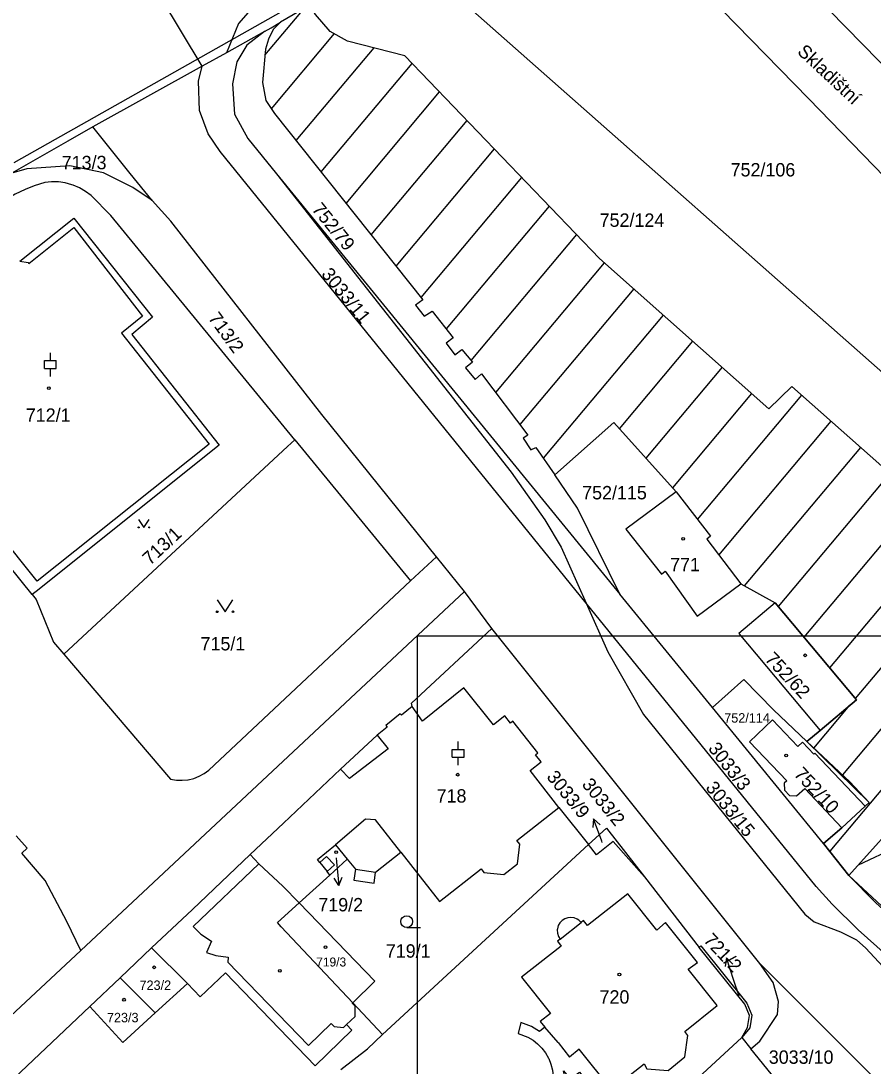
# Model space of a CAD drawing. Extents: x -496682 to -495776, y -1088797 to -1088018.
# Drawn here: x -496607.7 to -496499.5, y -1088218.9 to -1088086.1 of the extents above; entities that cross this region are included whole.
import ezdxf

# ---------------------------------------------------------------- set-up
doc = ezdxf.new("R2010")
doc.units = 0
for name, color, linetype in [('Hranice parcel', 7, 'Continuous'), ('Parcelní čísla', 7, 'Continuous'), ('Pop  PČ popisy', 7, 'Continuous'), ('Vnitřní kresba', 7, 'Continuous'), ('Vrstva 20', 7, 'Continuous'), ('Vrstva 54', 7, 'Continuous'), ('Vrstva 63', 7, 'Continuous'), ('Značky budov', 7, 'Continuous'), ('Značky kultur', 7, 'Continuous')]:
    doc.layers.add(name, color=color, linetype=linetype)

msp = doc.modelspace()

# ---------------------------------------------------------------- linework, layer by layer
at = {"layer": 'Hranice parcel'}
for p, q in [((-496584.7, -1088091.9), (-496593.73, -1088076.81)), ((-496571.02, -1088084.13), (-496574.77, -1088086.3)), ((-496580.1, -1088086.44), (-496581.64, -1088090.19)), ((-496576.81, -1088087.49), (-496581.64, -1088090.19)), ((-496581.64, -1088090.19), (-496584.7, -1088091.9)), ((-496584.7, -1088091.9), (-496598.59, -1088099.57)), ((-496585.17, -1088093.8), (-496584.7, -1088091.9)), ((-496575.26, -1088105.56), (-496531.65, -1088158.94)), ((-496572.95, -1088139.33), (-496586.65, -1088122.62)), ((-496572.95, -1088139.33), (-496558.23, -1088157.28)), ((-496554.95, -1088154.2), (-496558.23, -1088157.28)), ((-496551.4, -1088158.61), (-496554.95, -1088154.2)), ((-496583.85, -1088181.29), (-496558.23, -1088157.28)), ((-496521.83, -1088161.73), (-496516.3, -1088157.66)), ((-496516.3, -1088157.66), (-496511.91, -1088160.04)), ((-496600.11, -1088204.23), (-496551.4, -1088158.61)), ((-496547.92, -1088163.3), (-496551.4, -1088158.61)), ((-496519.86, -1088173.37), (-496531.65, -1088158.94)), ((-496513.88, -1088205.89), (-496547.92, -1088163.3)), ((-496602.29, -1088166.59), (-496588.72, -1088182.44)), ((-496505.76, -1088190.64), (-496519.86, -1088173.37)), ((-496506.2, -1088176.26), (-496507.89, -1088177.69)), ((-496539.38, -1088186.07), (-496535.62, -1088190.77)), ((-496500.47, -1088185.9), (-496503.43, -1088188.63)), ((-496503.43, -1088188.63), (-496505.76, -1088190.64)), ((-496606.96, -1088191.2), (-496608.33, -1088189.64)), ((-496561.79, -1088214.91), (-496535.62, -1088190.77)), ((-496566.28, -1088192.63), (-496568.5, -1088194.63)), ((-496572.41, -1088198.18), (-496568.5, -1088194.63)), ((-496528.52, -1088194.88), (-496521.57, -1088203.83)), ((-496600.11, -1088204.23), (-496610.33, -1088213.73)), ((-496591.15, -1088203.89), (-496595.15, -1088207.68)), ((-496591.15, -1088203.89), (-496586.58, -1088208.4)), ((-496595.15, -1088207.68), (-496598.99, -1088211.34)), ((-496595.15, -1088207.68), (-496590.7, -1088212.15)), ((-496586.58, -1088208.4), (-496590.7, -1088212.15)), ((-496598.99, -1088211.34), (-496611.67, -1088223.3)), ((-496561.79, -1088214.91), (-496565.59, -1088210.86)), ((-496516.14, -1088215.29), (-496545.84, -1088242.49)), ((-496516.14, -1088215.29), (-496515, -1088216.7)), ((-496510.2, -1088222.61), (-496515, -1088216.7))]:
    msp.add_line(p, q, dxfattribs=at)
for points in [[(-496529.16, -1088060.1), (-496522.91, -1088066.43), (-496519.74, -1088069.36), (-496513.72, -1088075.89), (-496502.91, -1088086.95), (-496490.59, -1088099.54)], [(-496539.32, -1088063.04), (-496541.74, -1088062.93), (-496544.5, -1088063.75), (-496558.08, -1088071.73), (-496573.82, -1088081.05), (-496576.28, -1088082.69), (-496577.99, -1088084.05), (-496580.1, -1088086.44)], [(-496539.03, -1088065.6), (-496535.97, -1088067.83), (-496531.62, -1088071.46), (-496507.63, -1088096.03), (-496473.26, -1088131.47)], [(-496559, -1088077.16), (-496484.87, -1088142.67), (-496473.26, -1088131.47)], [(-496449.81, -1088155.53), (-496454.1, -1088151.6), (-496460.56, -1088145.42), (-496469.27, -1088136.13), (-496476.41, -1088144.48), (-496483.29, -1088152.42), (-496496.71, -1088143.01), (-496497.27, -1088143.67), (-496509.81, -1088132.58), (-496512.72, -1088135.39), (-496534.24, -1088116.3), (-496558.95, -1088090.57), (-496566.25, -1088088.69), (-496568.44, -1088087.46), (-496570.32, -1088085.3), (-496571.02, -1088084.13)], [(-496574.77, -1088086.3), (-496575.71, -1088087.21), (-496576.29, -1088088.45), (-496576.66, -1088089.71), (-496577.03, -1088093.95), (-496576.63, -1088096.24), (-496575.54, -1088097.88), (-496556.69, -1088121.55), (-496557.59, -1088122.24), (-496556.5, -1088123.65), (-496555.48, -1088122.99), (-496552.81, -1088126.37), (-496553.73, -1088127.06), (-496552.61, -1088128.54), (-496551.71, -1088127.86), (-496550.38, -1088129.47), (-496551.26, -1088130.18), (-496550.05, -1088131.67), (-496549.21, -1088130.98), (-496543.32, -1088138.74), (-496543.92, -1088139.14), (-496542.96, -1088140.63), (-496542.32, -1088140.3), (-496539.92, -1088143.81)], [(-496576.81, -1088087.49), (-496575.96, -1088086.99), (-496574.77, -1088086.3)], [(-496576.81, -1088087.49), (-496579.05, -1088089.21), (-496580.3, -1088091.31), (-496580.87, -1088094.14), (-496580.61, -1088097.99), (-496578.92, -1088101.08), (-496575.26, -1088105.56)], [(-496535.94, -1088160.08), (-496582.43, -1088102.73), (-496583.94, -1088100.48), (-496585.03, -1088097.51), (-496585.17, -1088093.8)], [(-496598.59, -1088099.57), (-496601.77, -1088101.39), (-496608.89, -1088105.48)], [(-496591.05, -1088108.96), (-496593.86, -1088105.52), (-496598.59, -1088099.57)], [(-496591.05, -1088108.96), (-496593.52, -1088107.29), (-496597.24, -1088105.41), (-496601.51, -1088104.53), (-496607, -1088104.91), (-496608.89, -1088105.48)], [(-496598.83, -1088108.3), (-496599.53, -1088107.78), (-496600.29, -1088107.35), (-496601.08, -1088107.01), (-496601.29, -1088106.94), (-496602.12, -1088106.72), (-496602.98, -1088106.59), (-496603.85, -1088106.57), (-496604.72, -1088106.64), (-496606.05, -1088107.08), (-496607.21, -1088107.55), (-496608.47, -1088108.16), (-496609.68, -1088108.86), (-496610.16, -1088109.22), (-496610.57, -1088109.66), (-496610.74, -1088109.91), (-496611.03, -1088110.43), (-496611.23, -1088111), (-496611.33, -1088111.59)], [(-496575.26, -1088105.56), (-496545.47, -1088143.44), (-496541.17, -1088149.5), (-496539.1, -1088152.98), (-496535.94, -1088160.08)], [(-496586.65, -1088122.62), (-496596.3, -1088110.85), (-496598.83, -1088108.3)], [(-496554.95, -1088154.2), (-496569.51, -1088136.14), (-496588.7, -1088111.56), (-496591.05, -1088108.96)], [(-496607.87, -1088116.66), (-496601, -1088111.2), (-496591.02, -1088123.77), (-496593.66, -1088125.97), (-496582.54, -1088140.01), (-496605.81, -1088158.61), (-496606.3, -1088159)], [(-496606.3, -1088159), (-496617.15, -1088145.59), (-496618.65, -1088146.8), (-496619.26, -1088146.37), (-496619.37, -1088146.24), (-496621.25, -1088147.74), (-496621.51, -1088147.95), (-496621.62, -1088147.82), (-496622.15, -1088148.24), (-496627.2, -1088141.89), (-496626.66, -1088141.46), (-496626.77, -1088141.33), (-496626.5, -1088141.12), (-496624.56, -1088139.66), (-496624.44, -1088139.56), (-496628.56, -1088134.37)], [(-496539.92, -1088143.81), (-496532.42, -1088137.16), (-496524.49, -1088145.94)], [(-496602.29, -1088166.59), (-496573.88, -1088140.19), (-496572.95, -1088139.33)], [(-496531.65, -1088158.94), (-496537.04, -1088148.01), (-496539.92, -1088143.81)], [(-496524.49, -1088145.94), (-496530.88, -1088150.68), (-496526.37, -1088156.42)], [(-496524.49, -1088145.94), (-496520.15, -1088151.6), (-496520.61, -1088151.95), (-496516.3, -1088157.66)], [(-496526.37, -1088156.42), (-496525.89, -1088156.04), (-496521.83, -1088161.73)], [(-496606.3, -1088159), (-496605.78, -1088159.63), (-496603.61, -1088165.05), (-496602.29, -1088166.59)], [(-496535.94, -1088160.08), (-496533.17, -1088166.28), (-496528.64, -1088174.22), (-496508.14, -1088199.6), (-496506.98, -1088200.58), (-496503.63, -1088201.84), (-496501.59, -1088202.85), (-496500.38, -1088203.92), (-496493.36, -1088211.52), (-496474.31, -1088229.54), (-496444.2, -1088257.99), (-496416.61, -1088284.03), (-496413.37, -1088286.95)], [(-496413.37, -1088286.95), (-496422.7, -1088272.51), (-496424.74, -1088270.02), (-496501.36, -1088201.6), (-496504.67, -1088198.35), (-496506.73, -1088196.1), (-496535.94, -1088160.08)], [(-496511.91, -1088160.04), (-496516.53, -1088163.93), (-496506.2, -1088176.26)], [(-496511.91, -1088160.04), (-496501.59, -1088172.37), (-496506.2, -1088176.26)], [(-496558.05, -1088173.24), (-496558.11, -1088172.82), (-496547.92, -1088163.3)], [(-496507.89, -1088177.69), (-496512.14, -1088173.65), (-496515.88, -1088169.78), (-496519.86, -1088173.37)], [(-496539.38, -1088186.07), (-496543.06, -1088181.37), (-496541.64, -1088180.25), (-496542.35, -1088179.36), (-496542.05, -1088179.12), (-496545.24, -1088175.09), (-496545.54, -1088175.33), (-496546.26, -1088174.42), (-496547.71, -1088175.56), (-496551.45, -1088170.87), (-496556.73, -1088175.07), (-496558.05, -1088173.24)], [(-496558.05, -1088173.24), (-496559.39, -1088174.33), (-496559.54, -1088174.14), (-496561.39, -1088175.64), (-496561.23, -1088175.83), (-496562.5, -1088176.86), (-496567.13, -1088181.17), (-496574.38, -1088188.04), (-496578.61, -1088192.04), (-496585.95, -1088198.99), (-496591.15, -1088203.89)], [(-496500.47, -1088185.9), (-496506.88, -1088179.14), (-496507.01, -1088179.26), (-496508.45, -1088177.75), (-496509.05, -1088178.31), (-496512.25, -1088174.92), (-496515.17, -1088177.72), (-496510.42, -1088182.66), (-496510.78, -1088182.98), (-496510.72, -1088183.84), (-496510.09, -1088184.51), (-496509.22, -1088184.57), (-496508.15, -1088183.63), (-496503.43, -1088188.63)], [(-496507.89, -1088177.69), (-496502.43, -1088182.79), (-496499.96, -1088185.42), (-496500.47, -1088185.9)], [(-496588.72, -1088182.44), (-496587.99, -1088182.57), (-496587.25, -1088182.6), (-496586.52, -1088182.53), (-496586.5, -1088182.53), (-496585.78, -1088182.36), (-496585.09, -1088182.09), (-496584.44, -1088181.73), (-496583.85, -1088181.29)], [(-496566.28, -1088192.63), (-496565.24, -1088193.9), (-496565.43, -1088195.29), (-496562.87, -1088195.65), (-496562.68, -1088194.26), (-496559.49, -1088191.73), (-496554.58, -1088197.99), (-496549.28, -1088193.83), (-496548.95, -1088194.31), (-496546.38, -1088194.57), (-496544.64, -1088193.19), (-496544.34, -1088190.69), (-496544.73, -1088190.26), (-496539.38, -1088186.07)], [(-496502.56, -1088194.71), (-496494.62, -1088185.88), (-496475.92, -1088202.47), (-496475.59, -1088202.1), (-496472.44, -1088198.82), (-496390.14, -1088271.47), (-496393.43, -1088275.14), (-496397.84, -1088280.09)], [(-496535.62, -1088190.77), (-496533.34, -1088188.66), (-496528.52, -1088194.88)], [(-496600.11, -1088204.23), (-496601.92, -1088200.52), (-496604.66, -1088195.32), (-496607.61, -1088191.84), (-496606.96, -1088191.2)], [(-496568.5, -1088194.63), (-496568.85, -1088194.2), (-496567.92, -1088193.33), (-496568.9, -1088192.27), (-496569.77, -1088193.04), (-496570.07, -1088192.65), (-496567.77, -1088190.8), (-496566.28, -1088192.63)], [(-496528.52, -1088194.88), (-496532.5, -1088190.38), (-496534.6, -1088192.05), (-496535.62, -1088190.77)], [(-496505.76, -1088190.64), (-496505.13, -1088191.41), (-496502.56, -1088194.71)], [(-496502.56, -1088194.71), (-496499.18, -1088198.14), (-496484.17, -1088211.77), (-496484.46, -1088212.1)], [(-496565.59, -1088210.86), (-496574.67, -1088201.21), (-496575.15, -1088200.67), (-496572.41, -1088198.18)], [(-496572.41, -1088198.18), (-496562.76, -1088208.12), (-496565.59, -1088210.86)], [(-496540.11, -1088220.2), (-496538.7, -1088220.11), (-496538.8, -1088219.51), (-496537.96, -1088220.54), (-496536.76, -1088219.66), (-496534.07, -1088222.97), (-496532.71, -1088221.89), (-496528.54, -1088218.62), (-496528.23, -1088219.26), (-496525.5, -1088219.48), (-496523.39, -1088217.73), (-496523.01, -1088215), (-496523.4, -1088214.52), (-496519.3, -1088211.22), (-496522.96, -1088206.6), (-496521.78, -1088205.73), (-496525.83, -1088200.67), (-496526.94, -1088201.63), (-496530.63, -1088197.01), (-496535.75, -1088201.03), (-496536.25, -1088200.4), (-496536.58, -1088200.67)], [(-496536.58, -1088200.67), (-496536.87, -1088200.38), (-496537.08, -1088200.24), (-496537.46, -1088200.08), (-496537.86, -1088200.02), (-496538.27, -1088200.06), (-496538.63, -1088200.18), (-496538.98, -1088200.4), (-496539.27, -1088200.69), (-496539.47, -1088201.05), (-496539.58, -1088201.46), (-496539.6, -1088201.59), (-496539.58, -1088202.01), (-496539.46, -1088202.42), (-496539.25, -1088202.79)], [(-496539.25, -1088202.79), (-496539.58, -1088203.05), (-496539.1, -1088203.66), (-496544.13, -1088207.59), (-496540.46, -1088212.23), (-496541.79, -1088213.22), (-496541.18, -1088213.94), (-496541.84, -1088214.49), (-496542.89, -1088213.89), (-496544.22, -1088213.38), (-496544.58, -1088214.75), (-496543.34, -1088215.23)], [(-496521.57, -1088203.83), (-496521.34, -1088203.64), (-496515.5, -1088210.91), (-496514.87, -1088212.42), (-496515.14, -1088214.05), (-496516.14, -1088215.29)], [(-496516.14, -1088215.29), (-496515.43, -1088213.99), (-496515.18, -1088212.46), (-496515.76, -1088211.05), (-496521.57, -1088203.83)], [(-496515, -1088216.7), (-496513.86, -1088215.73), (-496511.62, -1088212.37), (-496511.5, -1088210.69), (-496512.18, -1088208.27), (-496513.88, -1088205.89)], [(-496489.52, -1088233.14), (-496498.76, -1088220.97), (-496513.88, -1088205.89)], [(-496586.58, -1088208.4), (-496584.97, -1088210.12), (-496581.74, -1088207.05), (-496570.35, -1088218.85), (-496565.71, -1088214.33), (-496566.38, -1088213.64), (-496565.27, -1088212.62), (-496565.28, -1088211.31), (-496565.66, -1088210.92), (-496565.59, -1088210.86)], [(-496590.7, -1088212.15), (-496594.81, -1088215.9), (-496598.99, -1088211.34)], [(-496567.11, -1088219.32), (-496563.72, -1088216.69), (-496561.79, -1088214.91)], [(-496543.34, -1088215.23), (-496542.68, -1088215.61), (-496542.09, -1088216.07), (-496541.56, -1088216.61), (-496541.1, -1088217.22), (-496540.71, -1088217.9), (-496540.69, -1088217.95), (-496540.4, -1088218.67), (-496540.21, -1088219.43), (-496540.11, -1088220.2)]]:
    msp.add_lwpolyline(points, dxfattribs=at)
at = {"layer": 'Pop  PČ popisy'}
for p, q in [((-496534.98, -1088187.49), (-496535.1, -1088188.6)), ((-496533.95, -1088190.31), (-496534.98, -1088187.49)), ((-496534.98, -1088187.49), (-496534.16, -1088188.26)), ((-496533.88, -1088190.5), (-496533.95, -1088190.31)), ((-496567.7, -1088192.43), (-496567.65, -1088192.97)), ((-496567.65, -1088192.97), (-496567.34, -1088195.96)), ((-496567.34, -1088195.96), (-496567.94, -1088195.01)), ((-496567.34, -1088195.96), (-496566.94, -1088194.91)), ((-496518.09, -1088205.16), (-496518.25, -1088206.26)), ((-496517.16, -1088208.01), (-496518.09, -1088205.16)), ((-496518.09, -1088205.16), (-496517.3, -1088205.95)), ((-496516.51, -1088210), (-496517.16, -1088208.01))]:
    msp.add_line(p, q, dxfattribs=at)
at = {"layer": 'Vnitřní kresba'}
for p, q in [((-496606.75, -1088116.93), (-496601.02, -1088112.36)), ((-496601.02, -1088112.36), (-496592.3, -1088123.64)), ((-496607.87, -1088116.66), (-496606.83, -1088116.82)), ((-496606.83, -1088116.82), (-496606.75, -1088116.93)), ((-496592.3, -1088123.64), (-496594.98, -1088125.8)), ((-496594.98, -1088125.8), (-496583.83, -1088139.89)), ((-496583.83, -1088139.89), (-496605.68, -1088157.3)), ((-496605.68, -1088157.3), (-496616.9, -1088143.28)), ((-496562.5, -1088176.86), (-496561.1, -1088178.58)), ((-496561.1, -1088178.58), (-496566, -1088182.37)), ((-496566, -1088182.37), (-496567.13, -1088181.17)), ((-496578.61, -1088192.04), (-496577.53, -1088193.19)), ((-496569.77, -1088193.04), (-496568.85, -1088194.2)), ((-496565.24, -1088193.9), (-496562.68, -1088194.26)), ((-496539.25, -1088202.79), (-496536.58, -1088200.67)), ((-496539.5, -1088215.91), (-496541.18, -1088213.94)), ((-496539.5, -1088215.91), (-496538.06, -1088217.76))]:
    msp.add_line(p, q, dxfattribs=at)
for points in [[(-496513.9, -1088047.1), (-496531.42, -1088056.78), (-496539.98, -1088064.95), (-496573.76, -1088084.47), (-496608.65, -1088104.15)], [(-496559.49, -1088191.73), (-496562.71, -1088187.6), (-496563.97, -1088187.55), (-496567.77, -1088190.8)], [(-496577.53, -1088193.19), (-496585.87, -1088201.16), (-496584.88, -1088202.15), (-496583.54, -1088203.02), (-496584.17, -1088204.48), (-496582.96, -1088204.87)], [(-496577.53, -1088193.19), (-496574.48, -1088196.05), (-496572.41, -1088198.18)], [(-496582.96, -1088204.87), (-496581.4, -1088205.05), (-496581.45, -1088205.72), (-496571.19, -1088216.3), (-496568.33, -1088213.51), (-496567.93, -1088213.88), (-496566.75, -1088213.98), (-496566.38, -1088213.64)], [(-496532.71, -1088221.89), (-496536.82, -1088216.76), (-496538.06, -1088217.76)]]:
    msp.add_lwpolyline(points, dxfattribs=at)
at = {"layer": 'Vrstva 20'}
for p, q in [((-496576.73, -1088090.48), (-496571.73, -1088084.52)), ((-496575.92, -1088097.29), (-496567.9, -1088087.74)), ((-496572.78, -1088101.33), (-496562.88, -1088089.54)), ((-496569.6, -1088105.32), (-496558.02, -1088091.52)), ((-496566.42, -1088109.31), (-496554.54, -1088095.15)), ((-496563.24, -1088113.3), (-496551.05, -1088098.77)), ((-496560.06, -1088117.29), (-496547.57, -1088102.4)), ((-496556.89, -1088121.28), (-496544.09, -1088106.03)), ((-496553.68, -1088125.24), (-496540.6, -1088109.66)), ((-496550.53, -1088129.27), (-496537.12, -1088113.28)), ((-496547.41, -1088133.33), (-496533.59, -1088116.86)), ((-496544.31, -1088137.41), (-496529.85, -1088120.18)), ((-496541.36, -1088141.68), (-496526.11, -1088123.49)), ((-496531.7, -1088137.94), (-496522.37, -1088126.81)), ((-496528.32, -1088141.68), (-496518.62, -1088130.13)), ((-496524.93, -1088145.43), (-496514.88, -1088133.45)), ((-496521.78, -1088149.45), (-496508.54, -1088133.68)), ((-496519.06, -1088153.99), (-496504.8, -1088136.99)), ((-496503.34, -1088181.92), (-496466.96, -1088138.57)), ((-496515.82, -1088157.9), (-496501.05, -1088140.31)), ((-496504.95, -1088191.62), (-496463.52, -1088142.25)), ((-496511.49, -1088160.52), (-496497.3, -1088143.62)), ((-496508.23, -1088164.42), (-496492.64, -1088145.84)), ((-496504.97, -1088168.31), (-496488.53, -1088148.72)), ((-496501.71, -1088172.21), (-496484.42, -1088151.6)), ((-496507, -1088178.51), (-496502.42, -1088173.05)), ((-496501.33, -1088193.32), (-496491.42, -1088188.7))]:
    msp.add_line(p, q, dxfattribs=at)
at = {"layer": 'Vrstva 54'}
msp.add_lwpolyline([(-496484.17, -1088211.77), (-496502.56, -1088194.71), (-496505.76, -1088190.64), (-496503.43, -1088188.63), (-496500.47, -1088185.9), (-496499.96, -1088185.42), (-496507.89, -1088177.69), (-496506.2, -1088176.26), (-496501.59, -1088172.37), (-496511.91, -1088160.04)], dxfattribs=at)
at = {"layer": 'Vrstva 63'}
msp.add_lwpolyline([(-496137.35, -1088164.24), (-496137.35, -1088461.24), (-496557.35, -1088461.24), (-496557.35, -1088164.24)], close=True, dxfattribs=at)
at = {"layer": 'Značky budov'}
for centre in [(-496604.19, -1088132.77), (-496523.6, -1088151.92), (-496508.12, -1088166.72), (-496510.53, -1088179.45), (-496552.25, -1088181.88), (-496567.69, -1088191.74), (-496569.03, -1088203.8), (-496590.81, -1088206.36), (-496574.84, -1088206.79), (-496531.71, -1088207.28), (-496594.64, -1088210.47)]:
    msp.add_circle(centre, 0.175, dxfattribs=at)
at = {"layer": 'Značky kultur'}
for p, q in [((-496604, -1088129.29), (-496604, -1088128.29)), ((-496604.75, -1088129.29), (-496603.25, -1088129.29)), ((-496604.75, -1088130.29), (-496604.75, -1088129.29)), ((-496604.75, -1088130.29), (-496603.25, -1088130.29)), ((-496604, -1088131.29), (-496604, -1088130.29)), ((-496603.25, -1088130.29), (-496603.25, -1088129.29)), ((-496552.19, -1088178.68), (-496552.19, -1088177.68)), ((-496552.94, -1088178.68), (-496551.44, -1088178.68)), ((-496552.94, -1088179.68), (-496552.94, -1088178.68)), ((-496551.44, -1088179.68), (-496551.44, -1088178.68)), ((-496552.94, -1088179.68), (-496551.44, -1088179.68)), ((-496552.19, -1088180.68), (-496552.19, -1088179.68)), ((-496558.72, -1088201.3), (-496556.97, -1088201.3))]:
    msp.add_line(p, q, dxfattribs=at)
for points in [[(-496592.78, -1088149.47), (-496592.11, -1088150.48), (-496591.44, -1088149.47)], [(-496582.8, -1088159.69), (-496581.8, -1088161.19), (-496580.8, -1088159.69)]]:
    msp.add_lwpolyline(points, dxfattribs=at)
for centre, radius in [((-496592.78, -1088150.48), 0.067), ((-496591.44, -1088150.48), 0.067), ((-496582.8, -1088161.19), 0.1), ((-496580.8, -1088161.19), 0.1), ((-496558.72, -1088200.55), 0.75)]:
    msp.add_circle(centre, radius, dxfattribs=at)

# ---------------------------------------------------------------- texts
at = {"layer": 'Parcelní čísla'}
for s, height, p in [('713/3', 1.7, (-496602.55, -1088104.97)), ('752/106', 1.7, (-496517.58, -1088105.89)), ('752/124', 1.7, (-496534.22, -1088112.29)), ('712/1', 1.7, (-496607.12, -1088137.06)), ('752/115', 1.7, (-496536.44, -1088146.91)), ('771', 1.7, (-496525.26, -1088156.04)), ('715/1', 1.7, (-496584.92, -1088166.1)), ('752/114', 1.2, (-496518.39, -1088175.27)), ('718', 1.7, (-496554.93, -1088185.43)), ('719/2', 1.7, (-496569.96, -1088199.25)), ('719/1', 1.7, (-496561.38, -1088205.13)), ('719/3', 1.139, (-496570.23, -1088206.25)), ('723/2', 1.2, (-496592.67, -1088209.23)), ('720', 1.7, (-496534.23, -1088210.97)), ('723/3', 1.2, (-496596.81, -1088213.34)), ('3033/10', 1.7, (-496512.73, -1088218.61))]:
    msp.add_text(s, height=height, dxfattribs=at).set_placement(p)
for s, rotation, p in [('752/79', 309, (-496570.87, -1088110.09)), ('3033/11', 309, (-496569.66, -1088118.34)), ('713/2', 306, (-496584.01, -1088123.9)), ('713/1', 43, (-496591.33, -1088155.36)), ('752/62', 313, (-496513.31, -1088167.28)), ('3033/3', 308, (-496520.51, -1088178.58)), ('752/10', 313, (-496509.63, -1088181.9)), ('3033/9', 309, (-496541.04, -1088182.2)), ('3033/2', 309, (-496536.56, -1088183.16)), ('3033/15', 309, (-496520.84, -1088183.57)), ('721/2', 313, (-496521.12, -1088202.99))]:
    msp.add_text(s, height=1.7, rotation=rotation, dxfattribs=at).set_placement(p)
at = {"layer": 'Pop  PČ popisy'}
msp.add_text('Skladištní', height=1.7, rotation=317, dxfattribs=at).set_placement((-496509.22, -1088090.18))

doc.saveas('drawing.dxf')
